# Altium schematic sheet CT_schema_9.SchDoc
size 254 x 194 mm
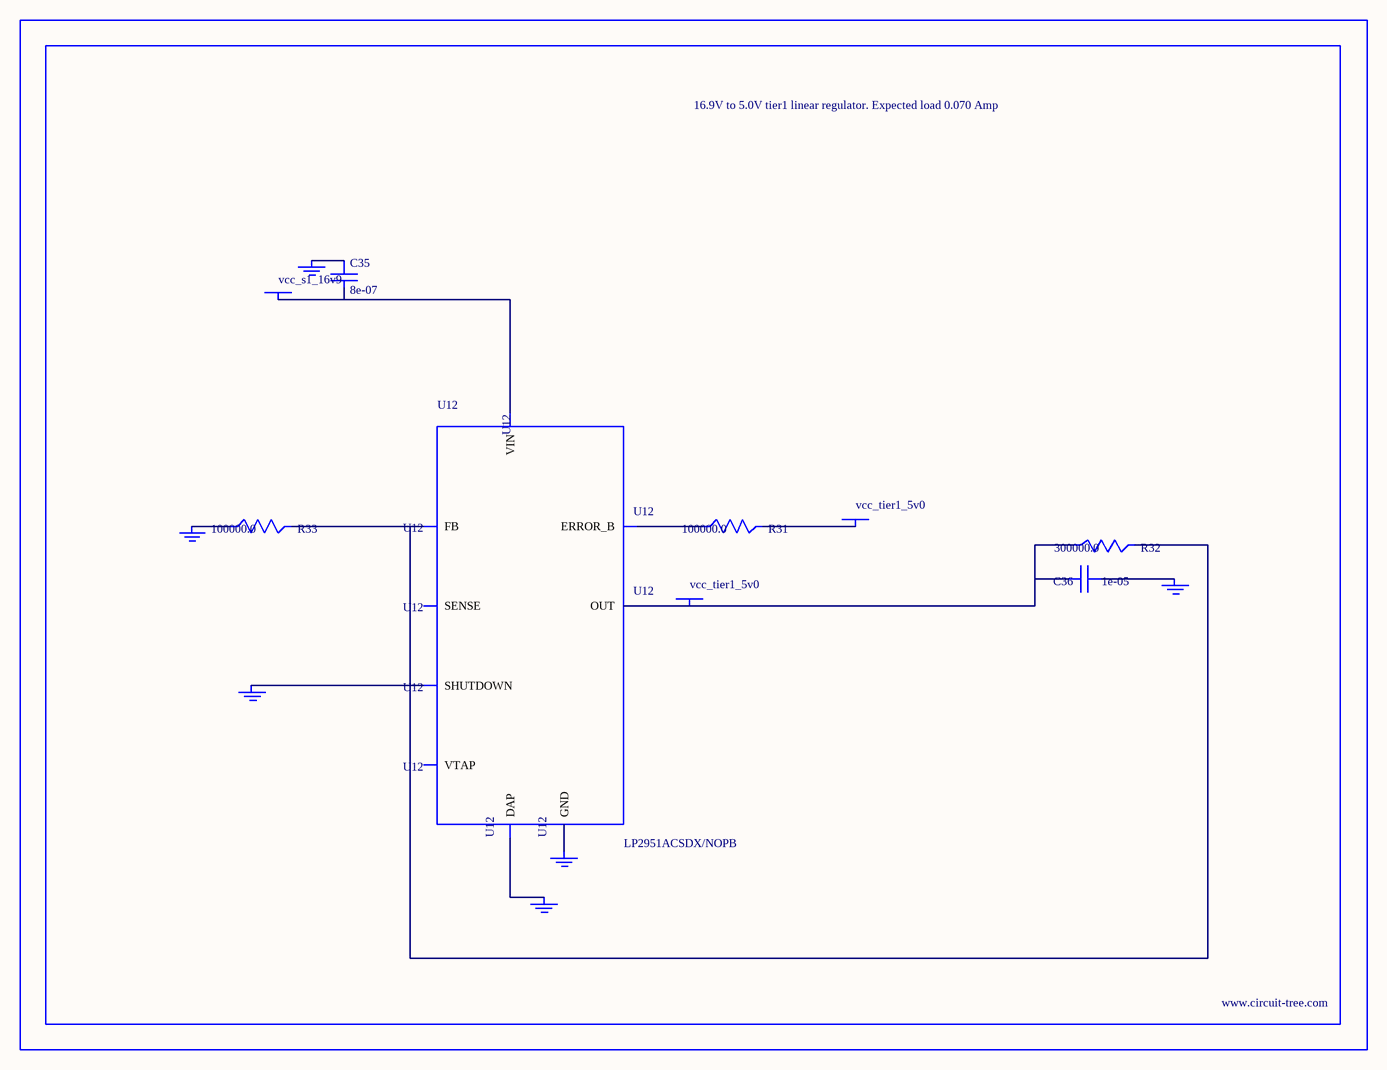
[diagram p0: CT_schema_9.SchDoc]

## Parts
BORDER8  (no value)
C35  8e-07  [R0603]
C36  1e-05  [C1210]
GND_INSTANCE_8_0  (no value)
GND_INSTANCE_8_1  (no value)
GND_INSTANCE_8_2  (no value)
GND_INSTANCE_8_3  (no value)
GND_INSTANCE_8_4  (no value)
GND_INSTANCE_8_5  (no value)
POWER_INSTANCE_8_0  vcc_tier1_5v0
POWER_INSTANCE_8_1  vcc_s1_16v9
POWER_INSTANCE_8_2  vcc_tier1_5v0
R31  100000.0  [R0603]
R32  300000.0  [R0603]
R33  100000.0  [R0603]
U12  LP2951ACSDX/NOPB  [WSON-8]

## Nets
NetC35_1: C35.1 GND_INSTANCE_8_3.0(GND)
NetC35_2: C35.2 POWER_INSTANCE_8_1.0(PWR) U12.8(VIN)
NetC36_1: C36.1 GND_INSTANCE_8_0.0(GND)
NetC36_2: C36.2 POWER_INSTANCE_8_2.0(PWR) R32.1 U12.1(OUT)
NetGND_INSTANCE_8_1_0: GND_INSTANCE_8_1.0(GND) U12.3(SHUTDOWN)
NetGND_INSTANCE_8_2_0: GND_INSTANCE_8_2.0(GND) R33.1
NetGND_INSTANCE_8_4_0: GND_INSTANCE_8_4.0(GND) U12.PAD(DAP)
NetGND_INSTANCE_8_5_0: GND_INSTANCE_8_5.0(GND) U12.4(GND)
NetPOWER_INSTANCE_8_0_0: POWER_INSTANCE_8_0.0(PWR) R31.2
NetR31_1: R31.1 U12.5(ERROR_B)
NetR32_2: R32.2 R33.2 U12.7(FB)

Not connected (* = marked no-connect by the designer): U12 2(SENSE) 6(VTAP)

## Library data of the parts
BORDER8 = BORDER_PAGE8
C35 = C35
C36 = GRM32DR61E106MA12L
GND_INSTANCE_8_0-GND_INSTANCE_8_5 = GND
POWER_INSTANCE_8_0-POWER_INSTANCE_8_2 = PWR
R31 R33 = RC0603JR-07100KL
R32 = RC0603JR-07300KL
